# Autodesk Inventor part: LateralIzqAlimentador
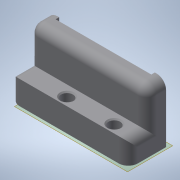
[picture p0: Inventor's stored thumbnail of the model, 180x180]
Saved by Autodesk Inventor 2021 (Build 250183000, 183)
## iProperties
Created: 2021-02
Part Number: LateralIzqAlimentador
Material: Genérico
Document SubType Name: Modeling
Designer: ATOUZA
Density: 1 g/cm^3
Appearance: Valor por defecto
Author: ATOUZA
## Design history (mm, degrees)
node "Plano de trabajo1"
sketch "Boceto1"
  geometry: L1 (25, 25.5)-(-25, 25.5); L2 (-25, 25.5)-(-25, 17.5); L3 (-25, 17.5)-(-20.25, 17.5); L4 (-20.25, 17.5)-(-20.25, 19); L5 (25, 25.5)-(25, 17.5); L6 (25, 17.5)-(20.25, 17.5); L7 (20.25, 17.5)-(20.25, 19); L8 (25, 25.5)-(-25, 25.5); L9 (-20.25, 19)-(20.25, 19); 1 further point
  constraints: 18 end point, 3 horizontal, 3 parallel, 2 perpendicular, 1 point on line
  dimensions: "d3" = 8 distance of L1.start L5.end; "d4" = 50 distance of L1.start L1.end; "d38" = 1.5 distance of L6.end L7.end; "d39" = 40.5 distance of L4.end L7.end; "d40" = 4.75 distance of L2.end L3.end; "d42" = 4.75 distance of L5.end L6.end
extrude "Extrusión2" new body sketch "Boceto1" distance "d17" = 25; taper "d18" = 0 deg
sketch "Boceto4"
  geometry: L1 (-25, 25.5)-(25, 25.5) reference; L2 (25, 25.5)-(-25, 25.5); L3 (-25, 25.5)-(-25, 33.5); L4 (-25, 33.5)-(25, 33.5); L5 (25, 33.5)-(25, 25.5); L6 (-20.25, 17.5)-(-20.25, 19) reference; L7 (-20.25, 19)-(19.75, 19); L8 (19.75, 19)-(19.75, -21); L9 (19.75, -21)-(-20.25, -21); L10 (-20.25, -21)-(-20.25, 19); L11 (0, -0.5)-(0, 29.5); L12 (0, 29.5)-(-25, 29.5); L13 (0, 29.5)-(25, 29.5); C1 r 2 at (-12.5, 29.5); C2 r 2 at (12.5, 29.5); 1 further point
  constraints: 22 end point, 4 midpoint, 4 parallel, 2 centre point, 2 horizontal, 2 perpendicular, 1 vertical
  dimensions: "d19" = 8 distance of L2.end L3.end; "d22" = 40 distance of L8.end L9.end; "d23" = 40 distance of L7.end L8.end; "d26" = 30 distance of L11.start L11.end; "d27" = 4 diameter of C1; "d28" = 4 diameter of C2
extrude "Extrusión3" join sketch "Boceto4" distance "d20" = 10; taper "d21" = 0 deg
sketch "Boceto5"
  geometry: L1 (-25, -33.5)-(25, -33.5) reference; L2 (-25, -25.5)-(25, -25.5) reference; L3 (6, -29.893)-(-15, -29.893); L4 (6, -29.893)-(25, -29.893); L5 (25, -17.5)-(25, -33.5) reference; L6 (4.811, 50.86)-(5.011, 50.86) reference; L7 (-4.5, -429.14)-(-4.5, 50.86) reference; L8 (15.5, -429.14)-(15.5, 50.86) reference; 3 further points
  constraints: 4 end point, 3 point on line, 2 horizontal, 2 midpoint
hole "Agujero2" sketch "Boceto5" diameter "d29" = 5; stored, may be unused: countersink angle "d33" = 90 deg, drill point angle "d35" = 118 deg; dims "d30" = 6, "d31" = 6, "d32" = 2, "d34" = 8
fillet "Empalme1" dims "d37" = 4
node "Sólido2"
node "Referencia3"
node "Referencia4"
node "Referencia5"
